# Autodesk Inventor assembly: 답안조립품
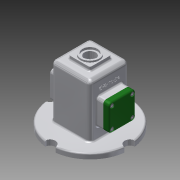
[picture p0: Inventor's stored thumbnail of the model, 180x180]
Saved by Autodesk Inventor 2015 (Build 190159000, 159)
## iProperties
Created: 2018-07
Part Number: 답안조립품
Document SubType Name: Assembly
Designer: pc
Author: pc
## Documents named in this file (5)
- C:\Users\pc\Desktop\480707V1016\답안조립품.iam
- C:\Users\pc\Desktop\480707V1016\본체.ipt
- C:\Users\pc\Desktop\480707V1016\뒤커버.ipt
- C:\Users\pc\Desktop\480707V1016\베어링 12x32x10.ipt
- C:\Users\pc\Desktop\480707V1016\볼트 M4.ipt
